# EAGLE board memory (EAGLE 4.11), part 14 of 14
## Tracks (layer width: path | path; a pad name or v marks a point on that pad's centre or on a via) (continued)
WTX*(JMP+JMS)  (via drill 0.61) (continued)
  Bottom 0.254: v321.94,356.87 323.85,356.87 v325.75,358.78 327.66,356.87 332.74,356.87 335.92,353.7 351.15,353.7 354.96,357.5 363.86,357.5 364.49,356.87 375.29,356.87 v377.82,359.41 | v379.73,369.57 380.37,370.21 389.25,370.21 389.89,369.57 396.88,369.57 398.14,370.84 A09.P2 | v157.48,95.25 156.21,93.98 150.5,93.98 149.86,93.34 147.32,93.34 146.05,94.61 141.6,94.61 E29.R2 | v157.48,138.43 208.28,138.43 209.55,137.16 v210.82,137.16 | v229.87,125.09 238.76,125.09 239.4,125.73 248.28,125.73 248.92,125.09 251.46,125.09 252.09,125.73 255.27,125.73 255.91,125.09 260.35,125.09 260.99,124.46 263.52,124.46 264.8,125.73 267.97,125.73 268.61,125.09 273.05,125.09 273.69,124.46 276.23,124.46 277.5,125.73 280.67,125.73 281.31,125.09 285.75,125.09 286.38,124.46 288.93,124.46 290.19,125.73 293.37,125.73 294,125.09 298.45,125.09 299.08,124.46 301.62,124.46 302.89,125.73 306.07,125.73 306.7,125.09 311.15,125.09 311.79,124.46 314.32,124.46 315.6,125.73 320.68,125.73 | 320.68,125.73 321.31,125.73 321.94,125.09 323.21,125.09 324.49,123.82 326.39,123.82 328.3,121.92 337.19,121.92 337.82,122.55 340.36,122.55 341,121.92 347.98,121.92 349.25,123.19 349.25,125.73 345.44,125.73 344.81,126.36 E13.D2 | 320.68,125.73 v320.68,126.36
WTX*(JMP+JMS)(B)
  Bottom 0.254: E30.V2 128.91,81.91 130.18,80.64 139.7,80.64 140.97,81.91 E29.V2 141.6,83.18 142.24,83.18 144.15,85.09 E29.U2
WTX*DCA
  Top 0.254: D08.R2 407.67,162.56 406.4,163.83 406.4,201.29 408.31,203.2 408.31,217.17 409.57,218.44 409.57,293.37 408.31,294.64 408.31,297.81 B08.R2
WTX*ISZ
  Route3 0.254: D08.J2 408.31,181.61 408.94,182.25 408.94,186.06 409.57,186.69 409.57,206.38 408.94,207.01 408.94,217.81 409.57,218.44 409.57,302.9 408.31,304.17 B08.N2
WTX*JMS  (via drill 0.61)
  Top 0.254: v323.85,381 323.85,414.66 326.39,417.2 390.52,417.2 v390.52,400.05 | v492.12,339.73 488.95,342.9 488.95,398.78 468.63,419.1 463.55,419.1 v463.55,401.96
  Route2 0.254: v323.85,381 319.4,381 A15.L2 | v415.93,204.47 416.56,205.1 426.08,205.1 v426.72,204.47
  Route3 0.254: v414.02,195.58 415.93,197.48 415.93,201.93 414.65,203.2 v415.93,204.47 | v487.68,210.19 495.3,217.81 495.3,242.57 492.12,245.75 492.12,250.82 493.39,252.09 492.12,253.36 v492.12,339.73
  Bottom 0.254: v390.52,400.05 394.97,400.05 A09.D2 395.61,400.69 398.14,400.69 399.42,401.96 401.95,401.96 405.76,398.15 415.93,398.15 419.74,401.96 427.36,401.96 427.99,401.32 434.34,401.32 437.51,398.15 440.06,398.15 440.69,398.78 447.04,398.78 450.21,401.96 452.75,401.96 454.66,400.05 455.93,400.05 457.2,401.32 462.92,401.32 v463.55,401.96 | v414.02,195.58 411.48,195.58 411.48,191.13 D08.E2 | v426.72,204.47 427.36,205.1 440.69,205.1 444.5,208.91 451.49,208.91 452.12,208.28 485.77,208.28 v487.68,210.19
WTX*OP2  (via drill 0.61)
  Top 0.254: v295.91,401.96 291.46,401.96 291.46,400.69 285.75,394.97 v285.75,394.34
  Route2 0.254: v414.65,170.18 415.29,169.54 421.64,169.54 426.72,164.47 427.36,164.47 429.89,167 434.98,167 436.25,165.73 D06.P2
  Route3 0.254: v414.65,170.18 412.75,172.09 412.75,204.47 411.48,205.74 411.48,220.34 412.75,221.61 412.75,342.27 387.35,367.67 387.35,379.73 v370.84,396.24
  Bottom 0.254: v370.84,396.24 365.12,401.96 354.96,401.96 351.15,398.15 342.26,398.15 341.63,398.78 339.09,398.78 338.45,398.15 329.56,398.15 328.93,398.78 326.39,398.78 325.75,398.15 316.87,398.15 316.23,398.78 313.69,398.78 313.06,398.15 304.17,398.15 300.36,401.96 v295.91,401.96 | v285.75,394.34 281.94,390.53 281.94,387.99 281.31,387.99 A18.J2
WTX*TAD  (via drill 0.61)
  Top 0.254: v236.22,314.33 241.3,319.41 v241.3,358.14 | v274.32,377.83 276.23,379.73 276.23,393.06 280.67,397.51 280.67,399.42 A18.D2
  Route2 0.254: v236.22,314.33 234.95,313.06 227.97,313.06 220.98,306.07 214,306.07 210.19,309.88 201.29,309.88 200.66,309.25 196.22,309.25 195.58,308.61 B25.M2 | v241.3,358.14 241.94,357.5 248.28,357.5 251.46,360.68 257.18,360.68 v274.32,377.83
ZI  (via drill 0.61)
  Top 0.254: v373.38,70.48 372.11,71.75 372.11,84.45 372.75,85.09 E11.U2 | v396.88,69.22 396.88,59.05 395.61,57.79 F09.D2
  Route2 0.254: v200.03,400.05 201.29,398.78 210.19,398.78 214,394.97 222.88,394.97 229.87,401.96 238.76,401.96 242.57,398.15 251.46,398.15 252.09,398.78 260.99,398.78 262.25,397.51 v263.52,397.51 | v497.2,240.03 498.48,238.76 498.48,220.34 v499.75,220.34 | v487.05,192.41 480.06,185.42 479.43,185.42 473.07,179.07 473.07,157.48 469.9,157.48 463.55,151.13 463.55,120.65 461.01,120.65 410.21,69.85 397.51,69.85 v396.88,69.22
  Route3 0.254: v200.03,400.05 200.03,401.96 190.5,401.96 158.75,370.21 158.75,358.14 158.12,357.5 158.12,345.44 155.57,342.9 155.57,326.39 156.84,325.12 156.84,321.31 B28.H2 | v263.52,397.51 270.51,404.5 276.86,404.5 277.5,405.13 286.38,405.13 287.02,404.5 289.56,404.5 297.81,412.75 v305.44,412.75 | v500.38,323.85 498.48,321.95 498.48,274.96 495.3,271.78 495.3,243.84 497.2,241.94 v497.2,240.03
  Bottom 0.254: v373.38,70.48 374.65,69.22 v396.88,69.22 | v305.44,412.75 317.5,412.75 318.13,413.39 330.2,413.39 330.83,414.02 364.49,414.02 365.12,413.39 375.29,413.39 375.92,414.02 398.78,414.02 399.42,413.39 437.51,413.39 438.79,412.12 480.69,412.12 501.65,391.16 501.65,323.85 v500.38,323.85 | v499.75,220.34 499.75,216.53 497.84,214.63 497.84,203.2 496.57,203.2 487.05,193.67 v487.05,192.41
